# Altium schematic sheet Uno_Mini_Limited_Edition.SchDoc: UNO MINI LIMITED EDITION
size A3; Author: Giuseppe Pinto; DocumentNumber: ABX00062; Revision: V0.4; SheetNumber: 1; SheetTotal: 1; RevAuthor: Giuseppe Pinto
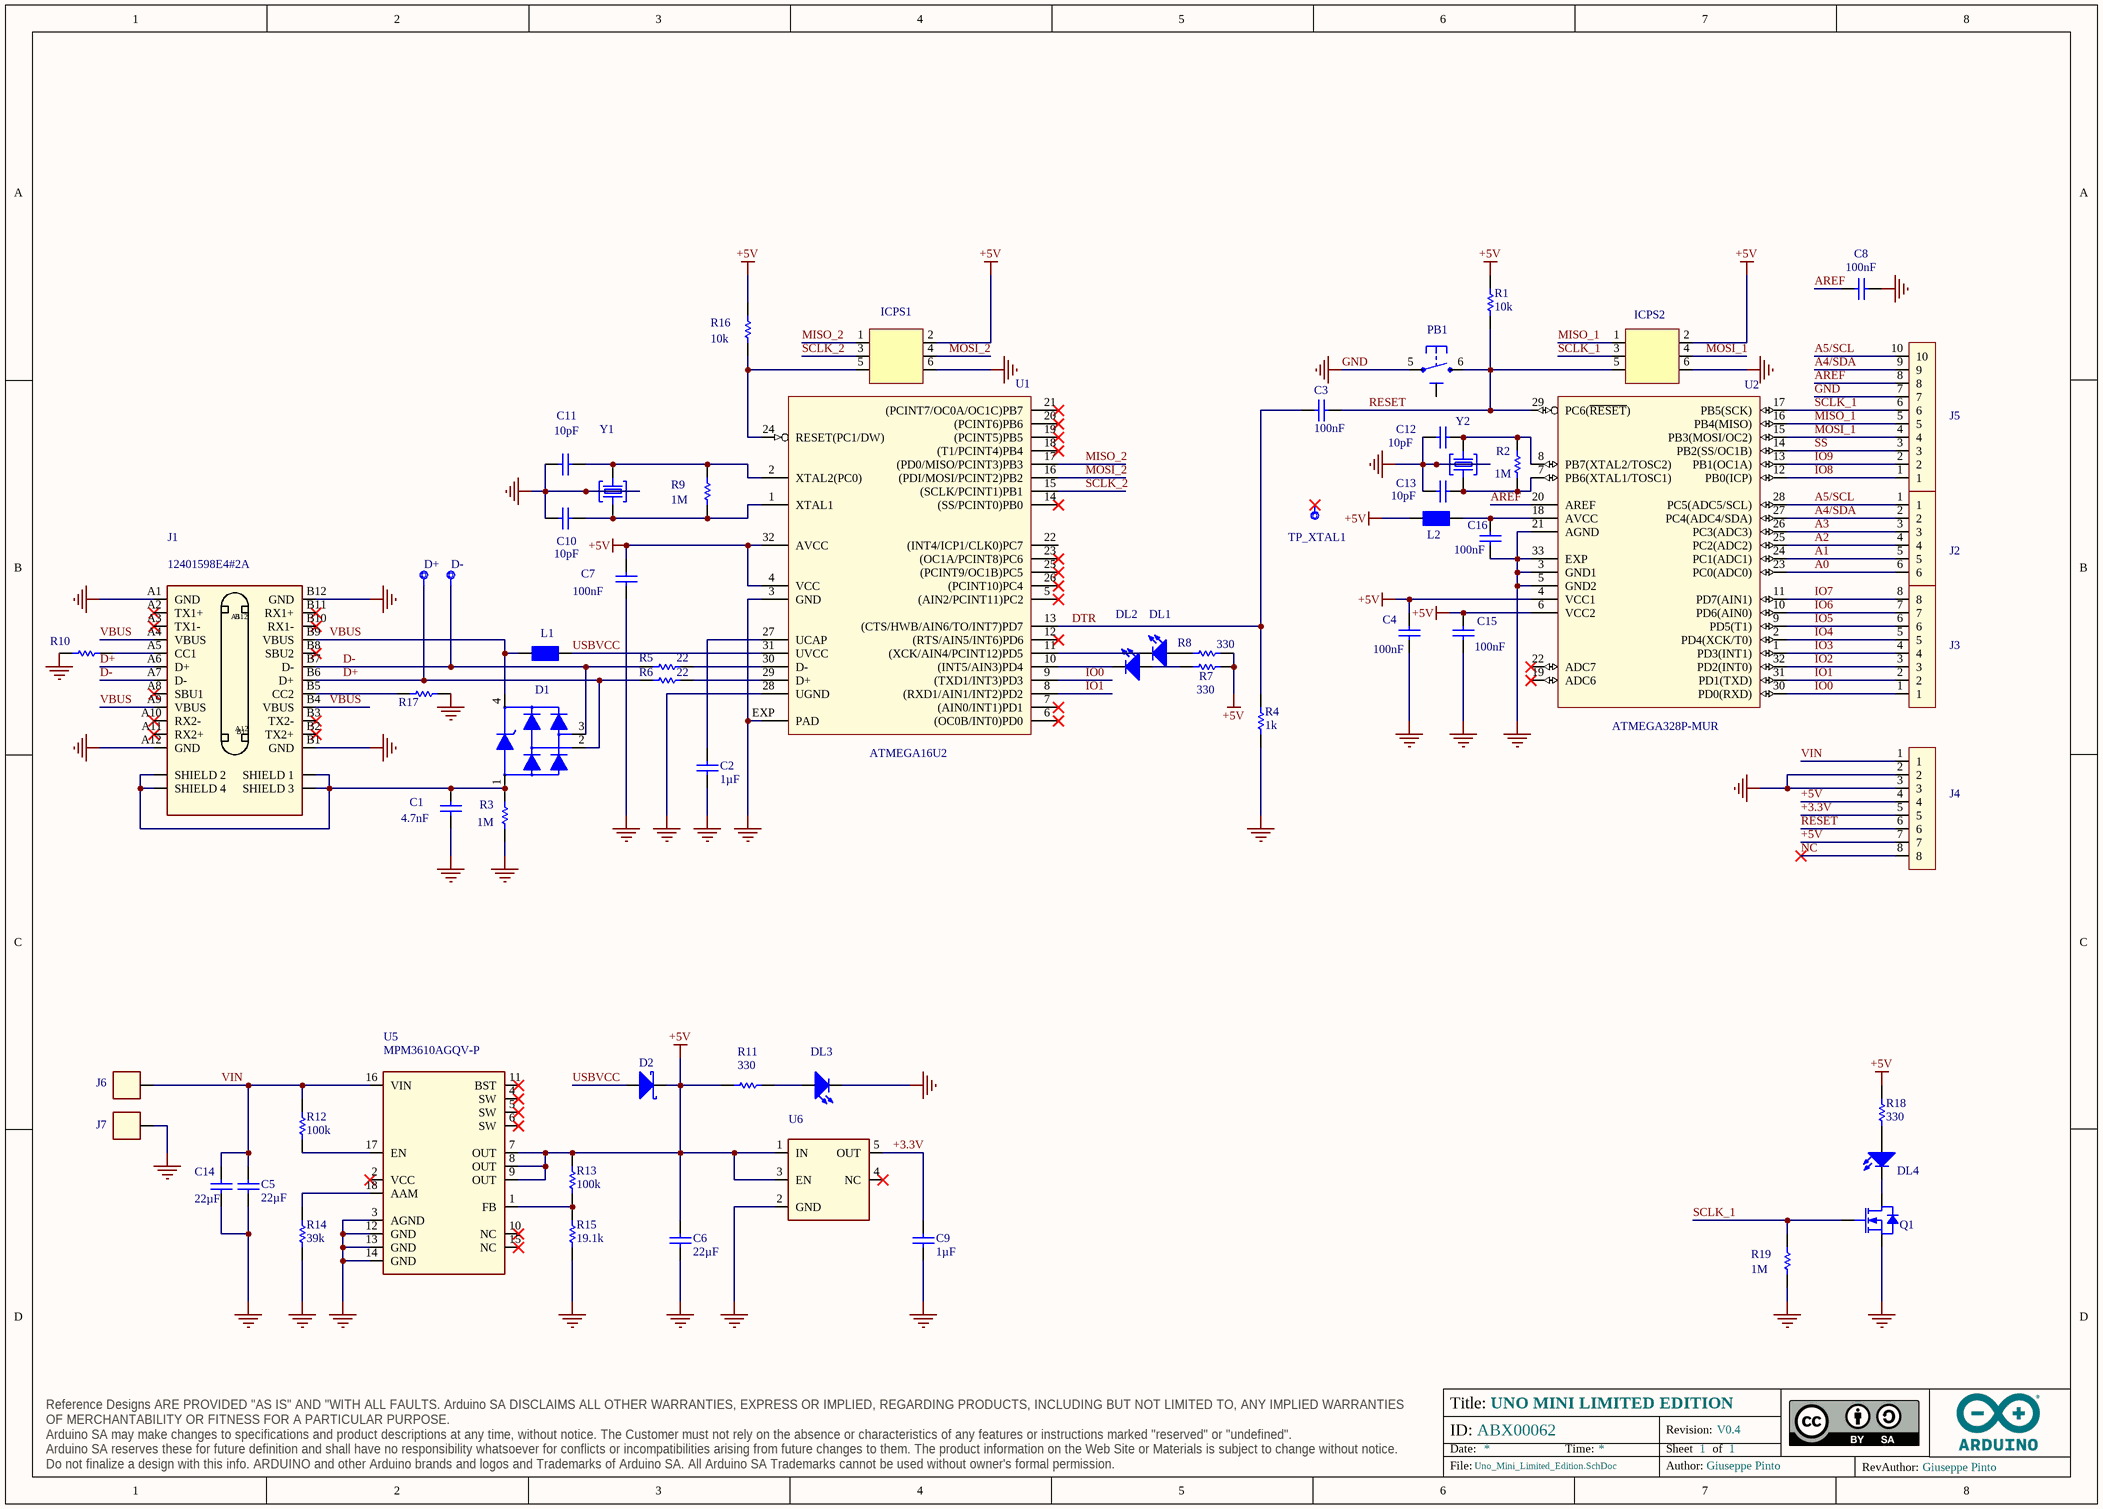
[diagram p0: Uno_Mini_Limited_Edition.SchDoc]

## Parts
C1  value 4.7nF  [CAP-0805]  (hidden comment: C0805C472KDRACTU)
C2  value 1µF  [CAP-0402]  (hidden comment: C0402C105K8PACTU)
C3  value 100nF  [CAP-0402]  (hidden comment: C0402C104K4RACTU)
C4  value 100nF  [CAP-0402]  (hidden comment: C0402C104K4RACTU)
C5  value 22µF  [CAP-0805]  (hidden comment: GRM219R61C226ME15K)
C6  value 22µF  [CAP-0805]  (hidden comment: GRM219R61C226ME15K)
C7  value 100nF  [CAP-0402]  (hidden comment: C0402C104K4RACTU)
C8  value 100nF  [CAP-0402]  (hidden comment: C0402C104K4RACTU)
C9  value 1µF  [CAP-0402]  (hidden comment: C0402C105K8PACTU)
C10  value 10pF  [CAP-0402]  (hidden comment: C0402H100J5GACTU)
C11  value 10pF  [CAP-0402]  (hidden comment: C0402H100J5GACTU)
C12  value 10pF  [CAP-0402]  (hidden comment: C0402H100J5GACTU)
C13  value 10pF  [CAP-0402]  (hidden comment: C0402H100J5GACTU)
C14  value 22µF  [CAP-0805]  (hidden comment: GRM219R61C226ME15K)
C15  value 100nF  [CAP-0402]  (hidden comment: C0402C104K4RACTU)
C16  value 100nF  [CAP-0402]  (hidden comment: C0402C104K4RACTU)
D1  PRTR5V0U2X,215  [SOT190P230X110-4N]  (value not drawn)
D2  PMEG6020AELRX  [SOD123-1]  (value not drawn)
D+  CMP-018-0005-A.3  [TP-1.00MM]  (value not drawn)  (no BOM)
D-  CMP-018-0005-A.3  [TP-1.00MM]  (value not drawn)  (no BOM)
DL1  KPT-1608SECK  [LEDC1608X80N-AK]  (value not drawn)
DL2  KPT-1608SECK  [LEDC1608X80N-AK]  (value not drawn)
DL3  HSMG-C190  [LEDC1608X80N-AK]  (value not drawn)
DL4  KPT-1608SECK  [LEDC1608X80N-AK]  (value not drawn)
ICPS1  PINHD-2X03-SM-TP  [2X03-TP]  (value not drawn)  (no BOM)
ICPS2  PINHD-2X03-SM-TP  [2X03-TP]  (value not drawn)  (no BOM)
J1  12401598E4#2A  [12401598E4#2A]
J2  RMS-106-02-L-S  [RMS-106-02-L-S-Footprint-1]  (value not drawn)
J3  RSM-108-02-L-S  [RMS-108-02-L-S-Footprint-1]  (value not drawn)
J4  RSM-108-02-L-S  [RMS-108-02-L-S-Footprint-1]  (value not drawn)
J5  RSM-110-02-L-S  [RMS-110-02-L-S-Footprint-1]  (value not drawn)
J6  HEADER_2.54mm_CASTELLATED_1x1  [PINHD-1X14_5VF]  (value not drawn)
J7  HEADER_2.54mm_CASTELLATED_1x1  [PINHD-1X14_5VF]  (value not drawn)
L1  BLM18PG471SN1D  [L-0603]  (value not drawn)
L2  BLM18PG471SN1D  [L-0603]  (value not drawn)
PB1  PTS820J25KSMTRLFS  [C&K_PTS820_NO_HOLES-1]  (value not drawn)
Q1  2N7002T-7-F  [SOT523]  (value not drawn)
R1  value 10k  [RES-0402]  (hidden comment: CRCW040210K0FKED)
R2  value 1M  [RES-0402]  (hidden comment: CRCW04021M00FKED)
R3  value 1M  [RES-0402]  (hidden comment: CRCW04021M00FKED)
R4  value 1k  [RES-0402]  (hidden comment: CRCW04021K00FKEDC)
R5  value 22  [RES-0402]  (hidden comment: CRCW040222R0JNEDC)
R6  value 22  [RES-0402]  (hidden comment: CRCW040222R0JNEDC)
R7  value 330  [RES-0402]  (hidden comment: CRCW0402330RJNED)
R8  value 330  [RES-0402]  (hidden comment: CRCW0402330RJNED)
R9  value 1M  [RES-0402]  (hidden comment: CRCW04021M00FKED)
R10  RC0402FR-075K1L  [RES-0402]  (value not drawn)
R11  value 330  [RES-0402]  (hidden comment: CRCW0402330RJNED)
R12  value 100k  [RES-0402]  (hidden comment: CRCW0402100KFKEDC)
R13  value 100k  [RES-0402]  (hidden comment: CRCW0402100KFKEDC)
R14  value 39k  [RES-0402]  (hidden comment: CRCW040239K0FKED)
R15  value 19.1k  [RES-0402]  (hidden comment: CRCW040219K1FKEDC)
R16  value 10k  [RES-0402]  (hidden comment: CRCW040210K0FKED)
R17  RC0402FR-075K1L  [RES-0402]  (value not drawn)
R18  value 330  [RES-0402]  (hidden comment: CRCW0402330RJNED)
R19  value 1M  [RES-0402]  (hidden comment: CRCW04021M00FKED)
TP_XTAL1  CMP-018-0005-A.3  [TP-1.00MM]  (value not drawn)  (no BOM)
U1  ATMEGA16U2  [ATMEL_QFN32]
U2  ATMEGA328P-MUR  [ATMEGA328P-MUR-Footprint-1]
U5  MPM3610AGQV-P  [POWER-LQFN20]
U6  AP2112K-3.3TRG1  [SOT25]  (value not drawn)
Y1  CX3225SB16000D0GZJC1  [CX3225SB16000D0GZJC1]  (value not drawn)
Y2  CX3225SB16000D0GZJC1  [CX3225SB16000D0GZJC1]  (value not drawn)

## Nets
+5V: C4.2 C6.2 C7.2 C15.2 D2.C ICPS1.2 ICPS2.2 J4.4 J4.7 L2.1 R1.2 R7.2 R8.1 R11.2 R13.2 R16.2 R18.1 U1.4(VCC) U1.32(AVCC) U2.4(VCC1) U2.6(VCC2) U5.7(OUT) U5.8(OUT) U5.9(OUT) U6.1(IN) U6.3(EN)
GND: C1.1 C2.1 C4.1 C5.1 C6.1 C7.1 C8.2 C9.1 C10.1 C11.1 C12.1 C13.1 C14.1 C15.1 C16.1 DL3.C ICPS1.6 ICPS2.6 J1.A1(GND) J1.A12(GND) J1.B1(GND) J1.B12(GND) J4.2 J4.3 J5.7 J7.1 PB1.5 Q1.S R3.1 R4.2 R10.1 R14.1 R15.1 R17.2 R19.1 U1.3(GND) U1.28(UGND) U1.EXP(PAD) U2.3(GND1) U2.5(GND2) U2.21(AGND) U2.33(EXP) U5.3(AGND) U5.12(GND) U5.13(GND) U5.14(GND) U6.2(GND) Y1.2 Y1.4 Y2.2 Y2.4
+3.3V: C9.2 J4.5 U6.5(OUT)
A0: J2.6 U2.23(PC0(ADC0))
A1: J2.5 U2.24(PC1(ADC1))
A2: J2.4 U2.25(PC2(ADC2))
A3: J2.3 U2.26(PC3(ADC3))
A4/SDA: J2.2 J5.9 U2.27(PC4(ADC4/SDA))
A5/SCL: J2.1 J5.10 U2.28(PC5(ADC5/SCL))
AREF: C8.1 J5.8 U2.20(AREF)
D+: D1.2 D+.X J1.A6(D+) J1.B6(D+) R6.1
D-: D1.3 D-.X J1.A7(D-) J1.B7(D-) R5.1
DTR: C3.1 R4.1 U1.13((CTS/HWB/AIN6/TO/INT7)PD7)
IO0: J3.1 U1.9((TXD1/INT3)PD3) U2.30(PD0(RXD))
IO1: J3.2 U1.8((RXD1/AIN1/INT2)PD2) U2.31(PD1(TXD))
IO2: J3.3 U2.32(PD2(INT0))
IO3: J3.4 U2.1(PD3(INT1))
IO4: J3.5 U2.2(PD4(XCK/T0))
IO5: J3.6 U2.9(PD5(T1))
IO6: J3.7 U2.10(PD6(AIN0))
IO7: J3.8 U2.11(PD7(AIN1))
IO8: J5.1 U2.12(PB0(ICP))
IO9: J5.2 U2.13(PB1(OC1A))
MISO_1: ICPS2.1 J5.5 U2.16(PB4(MISO))
MISO_2: ICPS1.1 U1.17((PD0/MISO/PCINT3)PB3)
MOSI_1: ICPS2.4 J5.4 U2.15(PB3(MOSI/OC2))
MOSI_2: ICPS1.4 U1.16((PDI/MOSI/PCINT2)PB2)
NC: J4.8
RESET: C3.2 ICPS2.5 J4.6 PB1.6 R1.1 U2.29(PC6(~{RESET}))
SCLK_1: ICPS2.3 J5.6 Q1.G R19.2 U2.17(PB5(SCK))
SCLK_2: ICPS1.3 U1.15((SCLK/PCINT1)PB1)
SS: J5.3 U2.14(PB2(SS/OC1B))
USBVCC: D2.A L1.2 U1.31(UVCC)
VBUS: D1.4 J1.A4(VBUS) J1.A9(VBUS) J1.B4(VBUS) J1.B9(VBUS) L1.1
VIN: C5.2 C14.2 J4.1 J6.1 R12.2 U5.16(VIN)
NetC1_2: C1.2 D1.1 J1.SHIELD_1 J1.SHIELD_2 J1.SHIELD_3 J1.SHIELD_4 R3.2
NetC2_2: C2.2 U1.27(UCAP)
NetC10_2: C10.2 R9.1 U1.1(XTAL1) Y1.1
NetC11_2: C11.2 R9.2 U1.2(XTAL2(PC0)) Y1.3
NetC12_2: C12.2 R2.2 U2.8(PB7(XTAL2/TOSC2)) Y2.3
NetC13_2: C13.2 R2.1 U2.7(PB6(XTAL1/TOSC1)) Y2.1
NetC16_2: C16.2 L2.2 U2.18(AVCC)
NetDL1_A: DL1.A R8.2
NetDL1_C: DL1.C U1.11((XCK/AIN4/PCINT12)PD5)
NetDL2_A: DL2.A R7.1
NetDL2_C: DL2.C U1.10((INT5/AIN3)PD4)
NetDL3_A: DL3.A R11.1
NetDL4_A: DL4.A R18.2
NetDL4_C: DL4.C Q1.D
NetICPS1_5: ICPS1.5 R16.1 U1.24(RESET(PC1/DW))
NetJ1_A5: J1.A5(CC1) R10.2
NetJ1_B5: J1.B5(CC2) R17.1
NetR5_2: R5.2 U1.30(D-)
NetR6_2: R6.2 U1.29(D+)
NetR12_1: R12.1 U5.17(EN)
NetR13_1: R13.1 R15.2 U5.1(FB)
NetR14_2: R14.2 U5.18(AAM)

Not connected (* = marked no-connect by the designer): J1 A2(TX1+)* A3(TX1-)* A8(SBU1)* A10(RX2-)* A11(RX2+)* B2(TX2+)* B3(TX2-)* B8(SBU2)* B10(RX1-)* B11(RX1+)*; PB1 PAD; TP_XTAL1 X*; U1 5((AIN2/PCINT11)PC2)* 6((OC0B/INT0)PD0)* 7((AIN0/INT1)PD1)* 12((RTS/AIN5/INT6)PD6)* 14((SS/PCINT0)PB0)* 18((T1/PCINT4)PB4)* 19((PCINT5)PB5)* 20((PCINT6)PB6)* 21((PCINT7/OC0A/OC1C)PB7)* 22((INT4/ICP1/CLK0)PC7) 23((OC1A/PCINT8)PC6)* 25((PCINT9/OC1B)PC5)* 26((PCINT10)PC4)*; U2 19(ADC6)* 22(ADC7)*; U5 2(VCC)* 4(SW)* 5(SW)* 6(SW)* 10(NC)* 11(BST)* 15(NC)*; U6 4(NC)*

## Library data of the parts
C1 = C0059-A.9: CAP CHIP 0805 4.7nF 1000V X7R 10%; Manufacturer: KEMET; Voltage: 1kV; Code Arduino: 0689
C2 C9 = C0017-A.9: CAP CHIP 0402 1uF 10V X5R 10%; Manufacturer: KEMET; Code Arduino: 0133
C3 C4 C7 C8 C15 C16 = C0012-A.9: CAP CHIP 0402 100nF 16V X7R 10%; Manufacturer: KEMET; Code Arduino: 0132
C5 C6 C14 = C0058-A.9: CAP CHIP 0805 22uF 16V X5R 20%; Manufacturer: Murata; Code Arduino: 2233
C10-C13 = C0006-A.9: CAP CHIP 0402 10pF 50V C0G 5%; Manufacturer: KEMET; Code Arduino: 3382
D1 = D0025-A.3: TVS ARRAY 4LIN.8kV 1pF SOT143B; Manufacturer: Nexperia; Code Arduino: 2209; Device Type: ESD protection
D2 = D0026-A.2: DIODE SCHOTTKY SMD 1A 40V SOD123FL; Manufacturer: Nexperia; Code Arduino: 2208
D+ D- TP_XTAL1 = UT0013-A.2: Test point 1.00mm
DL1 DL2 DL4 = L0006-A.4: LED SMD 0603 ORANGE601 250mcd 120^; Manufacturer: Kingbright; Code Arduino: 2207
DL3 = L0009-A.4: LED SMD 0603 GREEN/568 15mcd 120^; Manufacturer: Broadcom; Code Arduino: 2204
ICPS1 ICPS2 = J0066-A.3: 2X03 6 TEST POINTS; Code Arduino: DNP
J1 = J0220-A.5: CONN RCP USB3.1 TYPEC 24P SMD RA; Manufacturer: Amphenol ICC (Commercial Products); Connector Type: TELECOM AND DATACOM CONNECTOR; Code Arduino: J0220; Number of Contacts: 24
J2 = J0193-A.5: CONN PIN HEADER FEMALE SMD 1X6; Manufacturer: SAMTEC; Code Arduino: J0193
J3 J4 = J0194-A.7: CONN PIN HEADER FEMALE SMD 1X8; Manufacturer: SAMTEC; Code Arduino: J0194; Number of Contacts: 8; Contact Resistance: 10mR; Connector Type: BOARD CONNECTOR
J5 = J0196-A.5: CONN PIN HEADER FEMALE SMD 1X10; Manufacturer: SAMTEC; Code Arduino: J0196
J6 J7 = J0207-A.4: CONN THD HEADER 2.54mm CASTELLATED 1x1; Code Arduino: J0207
L1 L2 = I0006-A.3: FERRITE SMD 0603 470R 1A 0.2R; Manufacturer: Murata; DC Resistance (DCR): 200mR; Tolerance: 25%; Impedance: 470µH; Code Arduino: 2200; Test Frequency: 100MHz
PB1 = B0006-A.7: PUSHBUTTON SMD PTS820 NO HOLES; Manufacturer: C&K; Mechanical Life: 100000Cycles; Code Arduino: A5506; Actuator Type: Standard
Q1 = T0003-A.2: MOSFET N-CH 60V 115mA SOT523; Manufacturer: Diodes Inc.; Device Type: Mosfet N-CH SMD; Code Arduino: 2368
R1 R16 = R0003-A.5: RES CHIP 0402 10K 1% 1/16W; Manufacturer: Vishay; Power: 63mW; Code Arduino: 0136
R2 R3 R9 R19 = R0058-A.5: RES CHIP 0402 1M 1% 1/16W; Manufacturer: Vishay; Power: 63mW; Code Arduino: 0139
R4 = R0007-A.5: RES CHIP 0402 1K 1% 1/16W; Manufacturer: Vishay; Code Arduino: 0140; Power: 63mW
R5 R6 = R0010-A.5: RES CHIP 0402 22R 5% 1/16W; Manufacturer: Vishay; Code Arduino: 0468; Power: 63mW
R7 R8 R11 R18 = R0017-A.5: RES CHIP 0402 330R 5% 1/16W; Manufacturer: Vishay; Power: 63mW; Code Arduino: 2229
R10 R17 = R0210-A.6: RES CHIP 0402 5K1 1% 1/16W; Manufacturer: YAGEO; Code Arduino: R0210
R12 R13 = R0001-A.5: RES CHIP 0402 100K 1% 1/16W; Manufacturer: Vishay; Code Arduino: 0134; Power: 63mW
R14 = R0036-A.7: RES CHIP 0402 39K 1% 1/16W; Manufacturer: Vishay; Code Arduino: A5479; Power: 63mW
R15 = R0033-A.5: RES CHIP 0402 19k1 1% 1/16W; Manufacturer: Vishay; Code Arduino: A5369; Power: 63mW
U1 = U0035-A.7: IC ATMEGA16U2; Manufacturer: Microchip; Device Type: MCU
U2 = U0037-A.7: IC MICROCONTROLLER 8 bit; Manufacturer: Microchip; Core Architecture: PIC; Peripherals: Brown-out Detect/Reset,POR,PWM,WDT; Number of I/Os: 24; Oscillator Type: Internal; Memory Size: 3.5KB; Frequency: 20MHz; Memory Type: FLASH; Interface: I2C,SPI,UART,USART
U5 = U0075-A.8: IC StpDwn-CONV.21V 1.2A; Manufacturer: MPS; Number of Outputs: 1; Min Supply Voltage: 4.5V; Code Arduino: 2093; Voltage - Output 1: 18.48V; Output Voltage: 5.5V; Operating Supply Current: 200uA; Switching Frequency: 2MHz; Max Input Voltage: 21V
U6 = U0027-A.6: IC V-REG LDO 3V3 600mA +En  SOT25; Manufacturer: Diodes Inc; Code Arduino: 2199
Y1 Y2 = X0019-A.4: CRYSTAL 16.0000MHZ 8PF SMD; Manufacturer: Kyocera International Inc. Electronic Components; Code Arduino: X0019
